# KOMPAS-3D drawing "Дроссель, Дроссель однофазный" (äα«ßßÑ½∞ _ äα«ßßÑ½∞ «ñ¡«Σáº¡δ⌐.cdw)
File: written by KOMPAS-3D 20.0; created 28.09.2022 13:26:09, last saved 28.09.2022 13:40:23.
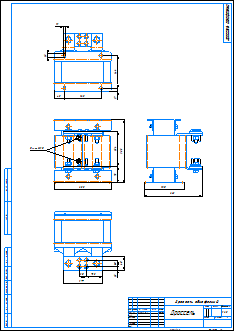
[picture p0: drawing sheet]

Sheet 1: A2, portrait

Document properties: Автор: admin; Полное имя файла: C:\Users\ceh\Desktop\Уралов\Шлюз\Дроссель _ Дроссель однофазный.cdw

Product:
- Part/product: Дроссель  | designation Дроссель однофазный
    Масса: 74.2568
  - Component [standard]: Болт М10-6gx120 (S16) ГОСТ 7798-70  | qty 4  | Масса: 0.08372; Раздел спецификации: Стандартные изделия; Рассекать на разрезах: no; source file: ..\..\..\..\..\Program Files\ASCON\KOMPAS-3D v20\Libs\PARTLib\DATA\vault\Methods\Kompas\3D\PLib_Bolt_1_900.m3d
  - Component [standard]: Шайба A 10.37 ГОСТ 10450-78  | qty 24  | Материал: АД1 ГОСТ 4784-97 (density 1000 kg/m3); Масса: 0.00210856; Раздел спецификации: Стандартные изделия; Рассекать на разрезах: no; source file: ..\..\..\..\..\Program Files\ASCON\KOMPAS-3D v20\Libs\PARTLib\DATA\vault\Methods\Kompas\3D\PLib_Washer_1_712.m3d
  - Component [standard]: Болт М10x1x45 ГОСТ Р 50790-95  | qty 8  | Масса: 0.0386; Раздел спецификации: Стандартные изделия; Рассекать на разрезах: no; source file: ..\..\..\..\..\Program Files\ASCON\KOMPAS-3D v20\Libs\PARTLib\DATA\vault\Methods\Kompas\3D\PLib_Bolt_1_ISO_1100.m3d
  - Component [standard]: Болт ГОСТ 32484.3 - М14 x 55 - HR  | qty 4
      Материал: Не определено (density 1000 kg/m3)
      Масса: 0.0127554
      Раздел спецификации: Стандартные изделия
      Рассекать на разрезах: no
      additional columns: ГОСТ 32484.3-2013
      source file: ..\..\..\..\..\Program Files\ASCON\KOMPAS-3D v20\Libs\PARTLib\DATA\vault\Methods\Kompas\3D\PLib_Bolt_1_ISO_1100.m3d
  - Component [standard]: Шайба A.14.37 ГОСТ 11371-78  | qty 8  | Материал: АД1 ГОСТ 4784-97 (density 1000 kg/m3); Масса: 0.008612; Раздел спецификации: Стандартные изделия; Рассекать на разрезах: no; source file: ..\..\..\..\..\Program Files\ASCON\KOMPAS-3D v20\Libs\PARTLib\DATA\vault\Methods\Kompas\3D\PLib_Washer_1_712.m3d
  - Component [standard]: Гайка М10-6H ГОСТ 15522-70  | qty 8  | Масса: 0.003416; Раздел спецификации: Стандартные изделия; Рассекать на разрезах: no; source file: ..\..\..\..\..\Program Files\ASCON\KOMPAS-3D v20\Libs\PARTLib\DATA\vault\Methods\Kompas\3D\PLib_Nut_OST92_900.m3d
  - Component [standard]: Шайба 10 ГОСТ 6402-70  | qty 12  | Масса: 0.00201; Раздел спецификации: Стандартные изделия; Рассекать на разрезах: no; additional columns: 10; source file: ..\..\..\..\..\Program Files\ASCON\KOMPAS-3D v20\Libs\PARTLib\DATA\vault\Methods\Kompas\3D\PLib_Washer_2_712.m3d
  - Body: Тело 3
      Масса: 0.833243
  - Component [standard]: Гайка М14-6H ГОСТ 5915-70  | qty 4  | Масса: 0.02891; Раздел спецификации: Стандартные изделия; Рассекать на разрезах: no; source file: ..\..\..\..\..\Program Files\ASCON\KOMPAS-3D v20\Libs\PARTLib\DATA\vault\Methods\Kompas\3D\PLib_Nut_OST92_900.m3d
  - Component [standard]: Шайба 14 ГОСТ 6402-70  | qty 4  | Масса: 0.00448; Раздел спецификации: Стандартные изделия; Рассекать на разрезах: no; additional columns: 14; source file: ..\..\..\..\..\Program Files\ASCON\KOMPAS-3D v20\Libs\PARTLib\DATA\vault\Methods\Kompas\3D\PLib_Washer_2_712.m3d
  - Body: Тело 4
      Масса: 0.624206
  - Body: Тело 5
      Масса: 0.624206
  - Body: Тело 1
      Масса: 1.08073
  - Body: Тело 2
      Масса: 70.0804
  - Component [standard]: Гайка М10-6H ГОСТ 2526-70  | qty 4  | Масса: 0.003713; Раздел спецификации: Стандартные изделия; Рассекать на разрезах: no; source file: ..\..\..\..\..\Program Files\ASCON\KOMPAS-3D v20\Libs\PARTLib\DATA\vault\Methods\Kompas\3D\PLib_Nut_OST92_900.m3d

Title block, sheet 1: Наименование: Дроссель; designation: Дроссель однофазный; Количество листов документа: 1; Форматы листов документа: A2; Разработал: Уралов Д.А.; Разработал, date: 28.09.22

Views: Проекционный вид 4
Referenced files in C:\Users\ceh\Desktop\Уралов\Шлюз\: Дроссель _ Дроссель однофазный.m3d
Referenced files in C:\Program Files\ASCON\KOMPAS-3D v20\Libs\PARTLib\DATA\vault\Methods\Kompas\3D\: PLib_Washer_1_712.m3d, PLib_Bolt_1_ISO_1100.m3d, PLib_Washer_2_712.m3d, PLib_Nut_OST92_900.m3d, PLib_Bolt_1_900.m3d
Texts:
  Шайба A.14.37 ГОСТ 11371-78
  Болт ГОСТ 32484.3 - М14 x 55 - HR
  Шайба 14 ГОСТ 6402-70
  Гайка М14-6H ГОСТ 5915-70
  Шайба A 10.37 ГОСТ 10450-78
  Шайба 10 ГОСТ 6402-70
  Гайка М10-6H ГОСТ 15522-70
  Болт М10x1x45 ГОСТ Р 50790-95
  Гайка М10-6H ГОСТ 2526-70
  Болт М10-6gx120 (S16) ГОСТ 7798-70
  Дроссель однофазный Дроссель
Dimensions and other numbers on the sheet: 165; 45; 146; 17; 18; 11; 1:2,5; 1; 28.09.22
